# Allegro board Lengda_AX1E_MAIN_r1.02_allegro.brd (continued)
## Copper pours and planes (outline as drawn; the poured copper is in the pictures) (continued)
GND on ART03 (solid shape): 66.49,71.68 77.48,71.68 77.96,71.2 77.96,69.79 76.85,68.68 64.61,68.68 63.44,69.85 62.37,69.85 61.96,70.26 61.36,70.26 61.14,70.48 61.14,70.86 75.8,70.86 75.81,70.8 75.82,70.75 75.84,70.7 75.86,70.65 75.9,70.61 75.94,70.57 75.98,70.54 76.03,70.51 76.08,70.49 76.14,70.48 76.19,70.48 76.25,70.49 76.3,70.5 76.35,70.52 76.4,70.55 76.44,70.59 76.48,70.63 76.51,70.67 76.53,70.72 76.55,70.78 76.56,70.83 76.56,70.89 76.55,70.94 76.53,70.99 76.51,71.04 76.48,71.09 76.44,71.13 76.4,71.17 76.35,71.2 76.3,71.22 76.25,71.23 76.19,71.24 76.14,71.24 76.08,71.23 76.03,71.21 75.98,71.18 75.94,71.15 75.9,71.11 75.86,71.07 75.84,71.02 75.82,70.97 75.81,70.91 75.8,70.86 61.14,70.86 61.14,71.84 61.88,72.58 65.59,72.58
GND on ART03 (solid shape): outline of 114 points within 46.61,34.29 56.81,48.94
GND on ART03 (solid shape): outline of 147 points within 121.49,79.89 131.74,90.32
GND on ART03 (solid shape): outline of 173 points within 50.99,13.8 57.82,27.84
GND on ART03 (solid shape): outline of 212 points within 200.78,95.62 213.72,106.46
GND on ART03 (solid shape): outline of 237 points within 38,10.23 49.59,37.31
GND on ART03 (solid shape): outline of 276 points within 22.48,44.9 39.82,67.14
GND on ART03 (solid shape): outline of 373 points within 43.84,80.14 59.93,110.02
GND on ART03 (solid shape): outline of 400 points within 34.79,90.22 55.9,111.67
GND on ART03 (solid shape): outline of 666 points within 55.51,78.75 84.97,102.32
GND on ART03 (solid shape): outline of 673 points within 192.69,52.16 197.91,58.9
GND on ART03 (solid shape): outline of 6369 points within 0.41,7.01 234.39,115.69
GND on GND04 (solid shape): outline of 86260 points within 0.41,7.01 234.39,115.69
GND on PWR05 (solid shape): outline of 63421 points within 0.41,7.01 234.39,115.69
GND on ART06 (solid shape): 138.28,44.32 138.34,44.41 138.45,44.39 141.69,41.14 141.69,39.08 140.91,38.29 140.91,32.64 140.9,32.55 140.91,32.45 140.91,22.64 145.24,18.3 146.75,18.3 146.96,18.09 149.28,18.09 150.17,17.2 150.17,16.67 150.03,16.53 150.03,11.12 153.34,7.82 190.33,7.82 190.57,8.07 194.01,8.07 194.07,8 195.62,8 196.21,7.41 202.54,7.41 203.13,8 205.57,8 205.62,7.98 205.74,7.96 205.87,7.98 205.9,7.98 205.92,7.96 206.21,7.68 231.89,7.68 234.22,10.01 234.33,10.03 234.39,9.94 234.39,7.06 234.38,7.02 234.34,7.01 149.71,7.01 149.67,7.02 149.66,7.06 149.66,17.51 140.11,17.51 140.07,17.52 140.06,17.56 140.06,39.1 139.6,41.83 138.29,44.26 138.28,44.27
GND on ART06 (solid shape): outline of 393 points within 100.84,72.96 113.47,77.86
GND on ART06 (solid shape): outline of 494 points within 143.64,30.19 234.39,115.69
GND on ART06 (solid shape): outline of 750 points within 23.69,89.82 39.37,106.7
GND on ART06 (solid shape): outline of 729 points within 23.77,70.16 39.49,88.01
GND on ART06 (solid shape): outline of 4841 points within 158.62,13.53 221.16,25.65
GND on ART06 (solid shape): outline of 5946 points within 0.41,7.01 149.71,115.69
GND on GND07 (solid shape): outline of 90744 points within 0.41,7.01 234.39,115.69
GND on ART03: 91.65,79.8 91.24,80.21 91.24,88.37 91.58,88.7 91.66,88.7 92.17,89.22 92.17,89.97 91.82,90.32 91.82,90.35 91.34,90.35 91.31,90.36 91.24,90.37 91.18,90.38 91.08,90.38 90.8,90.66 90.8,91.06 91.47,91.73 100.48,91.73 101.31,90.91 101.31,86.12 94.99,79.8
GND_EARTH on BOTTOM (solid shape): 83.56,97.03 83.56,92.13 83.34,91.91 80.63,91.91 79.99,92.55 79.99,97.08 80.51,97.6 83,97.6
GND_EARTH on BOTTOM (solid shape): 74.35,107.85 74.35,105.1 74.03,104.78 69.85,104.78 68.93,103.85 68.93,100.45 68.57,100.1 66.13,100.1 65.89,100.33 65.89,102.12 65.89,102.12 65.89,106.45 67.84,108.4 73.81,108.4
GND_EARTH on GND02 (solid shape): outline of 816 points within 66.52,84.89 82.17,104.41
GND_EARTH on PWR05 (solid shape): outline of 916 points within 65.88,84.9 83.59,108.39
GND_EARTH on GND07 (solid shape): outline of 916 points within 65.88,84.9 83.59,108.39
VCC1_USB2.0 on BOTTOM (solid shape): 57.18,99.24 57.18,95.24 56.79,94.85 46.76,94.85 46.42,95.19 46.42,96.56 46.9,97.04 50.53,97.04 50.58,96.99 50.58,96.98 51.15,96.41 54.78,96.41 55.02,96.66 55.02,99.25 55.14,99.37 57.05,99.37
VCC1_USB3.0 on TOP (solid shape): 22.07,110.79 22.07,106.37 23.22,105.22 23.22,95.33 22.86,94.97 17.01,94.97 16.65,95.32 16.65,96.53 16.87,96.75 20.97,96.75 21.24,97.01 21.24,104.71 19.78,106.16 19.78,107.32 18.46,108.64 18.45,108.66 18.44,108.68 18.44,110.2 18.52,110.28 19.85,110.28 20.38,110.82 22.04,110.82
VCC2_USB2.0 on TOP (solid shape): 53.65,113.37 53.65,111.71 53.59,111.64 49,111.64 48.67,111.31 48.67,107.42 44.3,103.05 44.3,95.58 43.02,94.3 36.24,94.3 35.9,94.64 35.9,96.74 36.3,97.14 41.01,97.14 41.64,97.77 41.64,103.71 46.14,108.21 46.14,112.17 47.48,113.51 48.65,113.51 48.66,113.52 53.5,113.52
VCC2_USB3.0 on TOP (solid shape): 39.29,111.67 39.29,110.07 39.08,109.87 34.82,109.87 34.2,109.25 34.2,108.38 34.82,107.76 34.96,107.76 35.08,107.64 35.08,106.81 34.53,106.26 34.53,95.74 33.73,94.94 27.55,94.94 27.35,95.14 27.35,96.89 27.71,97.25 31.98,97.25 32.33,97.59 32.33,105.24 31.43,106.14 31.43,108.68 32.33,109.58 32.33,110.9 33.55,112.12 38.84,112.12
VCC_8625 on BOTTOM (solid shape): 56.37,22.98 56.77,22.58 56.8,22.58 57.09,22.29 57.1,22.29 57.94,21.44 59.93,21.44 60.02,21.35 60.02,19.17 59.99,19.13 59.13,19.13 59.08,19.19 59.08,20.27 58.84,20.51 57.97,20.51 57.32,21.16 56.72,21.16 56.21,21.67 56.21,22.92 56.27,22.98
VCCIN_AUX on TOP (solid shape): 203.26,88.48 203.26,87.72 203.74,87.24 203.74,85.8 203.74,85.78 203.73,85.76 203.66,85.69 203.63,85.69 203.56,85.71 203.51,85.72 202.86,85.72 202.76,85.7 202.68,85.65 202.38,85.65 202.29,85.7 202.18,85.72 201.58,85.72 201.56,85.72 200.91,85.72 200.82,85.7 200.74,85.66 200.73,85.65 200.68,85.65 200.51,85.82 200.51,86.11 200.48,86.24 200.37,86.35 200.36,86.37 200.36,88.59 200.61,88.84 202.9,88.84
VCCIN_AUX on TOP (solid shape): 209.4,80.58 209.54,80.62 209.73,80.74 210.32,80.74 210.36,80.7 210.37,80.67 210.39,80.64 210.57,80.36 210.57,80.34 210.57,80.28 210.59,80.21 210.58,80.14 210.52,80.09 210.39,79.78 210.7,79.66 210.79,79.66 210.84,79.57 210.84,79.02 210.49,78.67 209.04,78.67 208.7,79.01 208.7,79.63 208.7,79.78 208.71,79.79 208.74,79.91 208.71,80.03 208.7,80.04 208.7,80.07 208.75,80.16 208.85,80.17 209.17,80.37 208.85,80.58 208.77,80.58 208.72,80.63 208.71,80.67 208.74,80.7 208.8,80.74 209.08,80.74
VCCIN_AUX on TOP (solid shape): outline of 96 points within 196.55,80.31 199.92,82.62
VCCIN_AUX on TOP (solid shape): outline of 198 points within 175.1,79.99 182.91,82.03
VCCIN_AUX on TOP (solid shape): outline of 374 points within 162.32,90.51 180.59,102.81
VCCIN_AUX on BOTTOM (solid shape): 209.82,79.43 210.92,79.43 211.09,79.26 211.09,78.42 210.54,77.88 208.86,77.88 208.58,78.16 208.58,79.29 208.84,79.56 209.68,79.56
VCCIN_AUX on BOTTOM (solid shape): outline of 741 points within 195.71,80.48 202.6,87.51
VCCIN_AUX on BOTTOM (solid shape): outline of 3223 points within 168.24,80.06 184.82,98.5
VCCIN_AUX on PWR05 (solid shape): outline of 8613 points within 167.82,68.78 221.33,97.7
VCCIN_AUX on ART06 (solid shape): outline of 1816 points within 168.31,80.01 182.91,96.86
VDD12 on BOTTOM (solid shape): 53.68,19.42 53.68,19.05 53.88,18.85 57.3,18.85 57.36,18.79 57.36,17.36 57.27,17.27 53.04,17.27 52.99,17.29 52.94,17.3 52.81,17.43 52.81,18.24 53.09,18.52 53.09,19.44 53.12,19.47 53.63,19.47
VIN_LCD on TOP (solid shape): 55.63,51.46 55.75,51.44 55.88,51.46 55.89,51.47 59.29,51.47 59.52,51.24 59.52,47.5 59.99,47.02 64.74,47.02 65.76,46.01 65.76,41.8 64.81,40.85 60.73,40.85 58.62,38.74 54.85,38.74 54.67,38.92 54.67,51.14 55,51.47 55.62,51.47
+V_ADP_IN on TOP (solid shape): 96.22,107.85 97.97,107.85 98.11,107.71 98.11,106.95 98.38,106.68 99.43,106.68 99.43,106.68 100.53,106.68 101.29,105.92 101.29,103.04 102.08,102.25 102.08,102.22 102.1,102.22 102.25,102.07 104.1,102.07 104.33,101.85 104.33,100.28 104.12,100.07 99.44,100.07 98.33,101.18 95.43,101.18 94.6,102.01 94.6,104.28 94.6,104.29 94.6,106.82 94.53,106.9 92.22,106.9 90.84,105.52 90.73,105.52 90.72,105.51 89.57,105.51 89.51,105.57 89.51,107.14 89.62,107.25 90.9,107.25 92.63,108.98 95.09,108.98
+V_ADP_IN on ART03 (solid shape): 104.35,102.4 104.35,100.74 103.8,100.19 96.51,100.19 96.33,100.37 96.33,102.61 96.69,102.97 103.78,102.97
+V_ADP_IN on ART06 (solid shape): 104.36,102.39 104.36,100.76 103.8,100.19 96.51,100.19 96.33,100.37 96.33,102.61 96.69,102.97 103.78,102.97
+V_LED on TOP (solid shape): outline of 435 points within 57.2,8.8 67.06,32.86
+VSYS_DCIN on TOP (solid shape): 71.02,50.65 71.02,48.28 70.47,47.74 60.62,47.74 60.01,48.35 60.01,50.7 60.6,51.29 70.37,51.29
+VSYS_DCIN on TOP (solid shape): 154.98,108.5 154.98,103.84 154.89,103.75 150.47,103.75 150,104.23 145.81,104.23 144.43,105.61 144.43,107.14 144.04,107.54 144.04,108.38 144.39,108.73 154.74,108.73
+VSYS_DCIN on TOP (solid shape): 176.78,111.67 176.78,106.46 176.38,106.06 172.16,106.06 170.78,107.44 166.29,107.44 165.52,108.21 165.52,111.36 165.95,111.79 169.95,111.79 170.84,112.67 175.78,112.67
+VSYS_DCIN on TOP (solid shape): 151.74,98.19 151.74,96.34 151.11,95.71 146.73,95.71 146.46,95.98 146.46,96.13 146.52,96.19 147.96,96.19 147.99,96.16 148.54,96.16 149.35,96.97 149.35,97.7 150.11,98.46 151.47,98.46
+VSYS_DCIN on TOP (solid shape): 209.4,113.57 209.4,112.51 209.85,112.06 209.85,111.47 209.67,111.29 209.67,107.1 209.28,106.7 199.76,106.7 199.14,107.32 199.14,111.6 198.88,111.87 197.74,111.87 197.59,112.02 197.59,112.83 198.35,113.59 209.39,113.59
+VSYS_DCIN on TOP (solid shape): outline of 598 points within 141.73,32.67 232.56,66.55
+VSYS_DCIN on TOP (solid shape): outline of 1379 points within 91.45,58.78 125.95,114.51
+VSYS_DCIN on BOTTOM (solid shape): 233.38,39.53 233.38,36.89 233.21,36.72 230.87,36.72 230.23,36.09 228.9,36.09 228.5,36.48 228.5,38.72 229.44,39.66 229.81,39.66 229.84,39.68 233.22,39.68
+VSYS_DCIN on BOTTOM (solid shape): outline of 6099 points within 67.04,34.45 210.06,115.69
EVDD10 on BOTTOM (solid shape): 66.22,68.24 66.22,63.8 66.02,63.6 63.99,63.6 63.42,64.17 63.42,64.95 63.04,65.34 63.04,68.23 63.16,68.36 66.11,68.36
FAN_VCC on TOP (solid shape): 233.8,29.57 233.8,29 233.8,25.34 233.57,25.12 232.82,25.12 232.73,25.2 232.73,27.81 232.04,28.5 232.04,29.6 232.16,29.71 233.65,29.71
IINA on TOP (solid shape): 56.29,14.36 56.29,10.74 56.18,10.63 54.36,10.63 54.21,10.78 54.21,13.36 55.27,14.41 56.23,14.41
LAN_N1 on BOTTOM (solid shape): 83.58,91.53 83.58,88.97 83.57,88.93 83.53,88.92 81.91,88.92 81.72,88.87 81.56,88.73 81.53,88.72 80.23,88.72 80.09,88.86 80.09,91.43 80.3,91.64 83.47,91.64
LCD_VCC on TOP (solid shape): 39.21,20.75 39.21,18.4 39.08,18.28 36.23,18.28 35.91,18.6 35.91,20.9 36.18,21.17 38.79,21.17
LCD_VCC on BOTTOM (solid shape): 56.09,16.25 56.09,12.68 56.24,12.53 56.24,11.5 56.13,11.39 54.96,11.39 54.77,11.58 54.77,16.25 54.97,16.45 55.89,16.45
LCD_VCC on ART06 (solid shape): outline of 621 points within 37.25,12.42 56.5,21.76
OVPA on TOP (solid shape): 69.35,28.57 69.35,27.74 69.1,27.5 66.98,27.5 66.83,27.64 66.83,28.59 66.99,28.75 69.17,28.75
PHASE1 on TOP (solid shape): 198.61,111.43 198.61,108.32 198.29,108 197.63,108 196.49,106.87 196.49,105.89 195.75,105.15 195.75,103.06 195.4,102.71 194.03,102.71 193.65,103.1 192.95,103.1 192.57,102.71 190.43,102.71 190.1,103.04 190.1,111.2 190.51,111.6 198.44,111.6
PHASE2 on TOP (solid shape): 188.37,110.68 188.37,103.7 187.54,102.88 184.57,102.88 184.43,103.02 183.76,103.02 183.69,102.94 183.69,102.82 183.4,102.53 179.89,102.53 178.99,103.42 178.14,103.42 177.95,103.61 177.95,104.92 177.27,105.6 177.27,109.43 177.63,109.79 178.71,109.79 178.72,109.79 182.44,109.79 183.83,111.19 187.86,111.19
PHASE3 on TOP (solid shape): outline of 138 points within 209.49,101.24 216.87,111.03
REGOUT on BOTTOM (solid shape): 70.83,69.08 70.83,67.89 69.94,66.99 69.18,66.99 68.37,66.18 68.37,64.06 68.02,63.72 66.69,63.72 66.62,63.79 66.62,63.97 66.61,63.98 66.61,68.32 67.06,68.76 70.23,68.76 70.61,69.13 70.78,69.13
RT6543A_PHASE on TOP (solid shape): outline of 136 points within 153.93,96.73 162.55,108.97
N501011 on TOP (solid shape): 146.28,95.8 146.28,89.03 145.65,88.41 142.78,88.41 142.49,88.69 142.48,88.7 142.48,88.72 142.48,95.58 142.83,95.93 146.15,95.93
N779371 on BOTTOM (solid shape): 3.15,93.51 3.87,93.51 4.22,93.16 4.22,92.62 4.21,92.62 4.21,91.9 5.02,91.1 6.99,91.1 7.94,92.05 8.7,92.05 8.91,91.84 8.91,90.2 8.79,90.08 4.6,90.08 3.2,91.48 1.86,91.48 1.33,92.01 1.33,93.78 1.65,94.1 2.55,94.1
N1274442 on TOP (solid shape): 128.92,60.01 129.35,59.58 129.35,56.2 128.8,55.64 125.06,55.64 124.89,55.69 124.71,55.67 124.61,55.64 120.75,55.64 120.75,55.64 115.9,55.64 115.64,55.89 115.64,56.87 115.65,56.88 115.66,56.9 115.76,57.16 115.66,57.43 115.65,57.45 115.64,57.46 115.64,58.09 115.65,58.1 115.65,58.41 115.86,58.62 120.69,58.62 121.21,59.14 123.42,59.14 123.45,59.14 123.47,59.11 124.2,58.9 124.3,59.66 124.29,59.67 124.29,59.71 124.6,60.02 128.92,60.02
N2010982 on TOP (solid shape): 91.28,86.24 91.28,83.59 90.92,83.23 82.99,83.23 82.92,83.29 82.92,86.04 83.2,86.32 83.22,86.33 83.24,86.33 91.18,86.33
N2484546 on TOP (solid shape): 20.6,59.75 20.6,58.35 20.32,58.07 19.34,58.07 19.04,58.37 19.04,59.46 16.29,62.21 15.42,62.21 15.29,62.34 15.29,63.3 15.4,63.41 16.94,63.41
N2507331 on TOP (solid shape): 72,46.09 72,39.77 71.98,39.74 71.98,30.28 71.14,29.43 67.65,29.43 67.22,29.86 67.22,32.56 66.08,33.71 66.08,33.73 65.68,34.13 65.68,40.17 67.24,41.73 67.24,45.91 67.84,46.51 71.58,46.51
N2514437 on BOTTOM (solid shape): 59.18,17.18 59.18,11.9 58.9,11.63 58.48,11.63 58.46,11.61 58.43,11.61 58.43,11.58 58.27,11.43 57.68,11.43 57.61,11.49 57.61,12.26 57.87,12.52 57.87,17.14 58.07,17.34 59.01,17.34
N2516589 on BOTTOM (solid shape): 56,20.82 57.15,20.82 57.4,20.57 57.4,19.43 57.31,19.34 54.29,19.34 54.2,19.42 54.2,20.8 54.43,21.03 54.43,21.43 54.5,21.5 55.31,21.5
N3254610 on TOP (solid shape): 104.08,99.5 104.08,96.34 103.77,96.03 100.5,96.03 100.28,96.25 100.28,97.64 100.28,97.64 100.28,98.42 100.24,98.46 99.04,98.46 98.91,98.6 98.91,99.65 99.04,99.78 103.8,99.78
N3254610 on ART03 (solid shape): 104.66,99.54 104.66,97.98 104.96,97.68 104.96,95.82 104.65,95.51 101.76,95.51 101.49,95.78 101.49,99.5 101.85,99.86 104.34,99.86
N3254610 on ART06 (solid shape): 105.14,99.43 105.14,95.76 104.9,95.51 101.76,95.51 101.49,95.78 101.49,99.5 101.85,99.86 104.72,99.86
N3254616 on TOP (solid shape): 98.74,100.09 98.74,98.52 98.95,98.31 99.9,98.31 100.01,98.2 100.01,96.25 99.85,96.08 92.5,96.08 92.5,96.09 91.75,96.09 91.01,96.83 91.01,99.85 91.68,100.52 98.32,100.52
N3254616 on ART03 (solid shape): 101.2,99.58 101.2,95.84 100.94,95.58 93.63,95.58 92.68,96.53 92.68,99.15 93.37,99.83 100.95,99.83
N7794586 on TOP (solid shape): 153.2,102.74 153.2,101.71 153.06,101.57 152.09,101.57 151.99,101.67 151.99,101.83 151.84,101.98 151.15,101.98 151.11,102.02 151.11,102.33 151.81,103.04 152.91,103.04
N20947999 on BOTTOM (solid shape): 218.24,12.31 218.24,8.47 217.46,7.69 216.8,7.69 216.72,7.61 214.82,7.61 214.81,7.61 214.69,7.63 214.57,7.61 214.57,7.61 211.01,7.61 211,7.61 210.88,7.63 210.76,7.61 210.76,7.61 208.64,7.61 208.6,7.65 208.6,9.19 208.62,9.22 208.65,9.24 209.48,9.24 209.53,9.28 209.56,9.3 209.6,9.28 210.55,8.33 211.58,8.33 212.03,8.78 212.03,9.28 212.16,9.41 215.41,9.41 215.62,9.62 215.62,12.34 215.95,12.67 217.87,12.67
N20949253 on TOP (solid shape): 144,78.25 145.77,78.25 145.9,78.12 145.9,76.13 145.46,75.69 142.49,75.69 142.36,75.83 142.36,77 142.82,77.46 142.83,77.46 143,77.63 143,77.99 143.27,78.26 143.99,78.26
N20949292 on TOP (solid shape): 154.1,78.82 154.1,77.15 154.02,77.07 149.4,77.07 149.07,77.39 147.95,77.39 147.94,77.38 147.9,77.38 147.77,77.51 147.77,78.16 147.85,78.24 148.58,78.24 149.37,79.04 153.88,79.04
N20955030 on TOP (solid shape): 177.43,104.68 177.43,103.41 177.26,103.24 177.26,102.53 177.17,102.44 176.47,102.44 176.25,102.66 176.25,104.63 176.44,104.82 177.28,104.82
N20968756 on TOP (solid shape): 88.92,107.01 88.92,100.39 88.16,99.64 84.72,99.64 84,100.36 84,103.6 84.6,103.6 84.6,103.52 84.61,103.44 84.63,103.36 84.66,103.29 84.69,103.22 84.74,103.15 84.78,103.08 84.84,103.02 84.9,102.97 84.96,102.93 85.03,102.89 85.11,102.85 85.18,102.83 85.26,102.81 85.34,102.8 85.42,102.8 85.5,102.8 85.58,102.82 85.66,102.84 85.73,102.87 85.8,102.9 85.87,102.95 85.93,103 85.99,103.05 86.04,103.11 86.09,103.18 86.12,103.25 86.15,103.33 86.18,103.4 86.19,103.48 86.2,103.56 86.2,103.64 86.19,103.72 86.18,103.8 86.15,103.87 86.12,103.95 86.09,104.02 86.04,104.09 85.99,104.15 85.93,104.2 85.87,104.25 85.8,104.3 85.73,104.33 85.66,104.36 85.58,104.38 85.5,104.4 85.42,104.4 85.34,104.4 85.26,104.39 85.18,104.37 85.11,104.35 85.03,104.31 84.96,104.27 84.9,104.23 84.84,104.18 84.78,104.12 84.74,104.05 84.69,103.98 84.66,103.91 84.63,103.84 84.61,103.76 84.6,103.68 84.6,103.6 84,103.6 84,104.88 84.82,105.71 84.87,105.71 84.87,105.75 86.49,107.38 88.55,107.38
N22198022 on TOP (solid shape): 133.86,84.46 133.86,81.58 133.5,81.23 125.58,81.23 125.09,80.73 124.09,80.73 123.9,80.92 123.9,81.74 123.9,81.74 123.9,82.05 128.18,82.05 128.19,81.99 128.2,81.94 128.22,81.89 128.25,81.84 128.28,81.79 128.32,81.75 128.37,81.72 128.41,81.7 128.47,81.68 128.52,81.67 128.58,81.67 128.63,81.67 128.69,81.69 128.74,81.71 128.78,81.74 128.83,81.77 128.86,81.81 128.89,81.86 128.92,81.91 128.93,81.96 128.94,82.02 128.94,82.07 128.93,82.13 128.92,82.18 128.89,82.23 128.86,82.28 128.83,82.32 128.78,82.35 128.74,82.38 128.69,82.4 128.63,82.42 128.58,82.42 128.52,82.42 128.47,82.41 128.41,82.39 128.37,82.37 128.32,82.34 128.28,82.3 128.25,82.25 128.22,82.21 128.2,82.15 128.19,82.1 128.18,82.05 123.9,82.05 123.9,83.69 125.09,84.88 133.44,84.88

Small or netless copper shapes (teardrops, artwork), in the pictures only: 2 on TOP, 2 on GND04, 23 on PWR05, 1 on ART06

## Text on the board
Ref Des/Silkscreen Bottom: EDID | BB | BC | BOTTOM | BA | V1.02 | BOT | 5000-0008-3782 | 2019.1009.1600 | BJ | AX1E_MAIN_PCB | REF | BH | BF | BE | INCODE
Ref Des/Silkscreen Top: AX1E_MAIN_PCB | TA | TW | TB | 5000-0008-3782 | 2019.1009.1600 | TOP | V1.02 | REF | TC | TE | TF | TH | TG | TJ | TK
User.36: FIGURE | SIZE | 9.84 | 15.75 | 27.56 | 31.5 | 37.4 | 39.4 | 51.18 | 62.99 | 86.61 | 90.55 | 133.86 | 149.61 | 39.37 | 43.0 | 43.31 | 63.0 | 78.74 | 125.98 | 59.06x23.62 | 82.68x66.93 | 94.49x39.37 | 98.43x35.43 | DRILL CHART: TOP to BOTTOM | ALL UNITS ARE IN MILS | TOLERANCE | +0.0/-0.0 | +3.0/-3.0 | +2.0/-2.0 | PLATED | NON-PLATED | QTY | 3288 | 1 | 754 | 10 | 22 | 18 | 8 | 3 | 2 | 4 | 7 | 6
